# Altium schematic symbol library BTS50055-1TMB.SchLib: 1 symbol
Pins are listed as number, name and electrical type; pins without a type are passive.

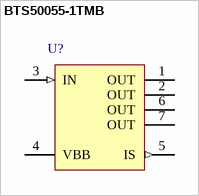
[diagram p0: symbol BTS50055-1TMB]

## BTS50055-1TMB
designator U?
Smart Highside High Current Power Switch Reversave, 1 Channel, 17 A Load Current, -40 to 150 degC, PG-TO220-7-11, Tube, Green; Manufacturer: Infineon; PartNumber: BTS50055-1TMB; Channels: 1; Green: TRUE; Group: Automotive Qualified; Load Current (typ): 17 A; Packing: Reel; Ptot (max): 170 W; Recommended Operating Voltage Max.: 34 V; Recommended Operating Voltage Min.: 5 V; RON @ 25degreesC: 6 mOhm; RON(max) @ 150degreesC: 10.5 mOhm; toff (max): 200 us; ton (max): 470 us
footprint INF-PG-TO220-7-11 (FM, 7-Leads, Body 10x9.25mm, Pitch 1.27mm)
pins: 1 OUT (power) "Output; output to the load; pin 1, 2, 6 and 7 must be externally shorted with each other especially in high current applications.", 2 OUT (power) "Output; output to the load; pin 1, 2, 6 and 7 must be externally shorted with each other especially in high current applications.", 3 IN (in) "Input; has an internal pull up; activates the power switch in case of short to ground", 4 VBB (power) "Supply voltage; positive power supply voltage; tab and pin 4 are internally shorted; in high current applications use the tab.", 5 IS (out) "Sense Output; Diagnostic feedback; provides a sense current proportional to the load current; zero current on failure (see Truth Table on page 7)", 6 OUT (power) "Output; output to the load; pin 1, 2, 6 and 7 must be externally shorted with each other especially in high current applications.", 7 OUT (power) "Output; output to the load; pin 1, 2, 6 and 7 must be externally shorted with each other especially in high current applications."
